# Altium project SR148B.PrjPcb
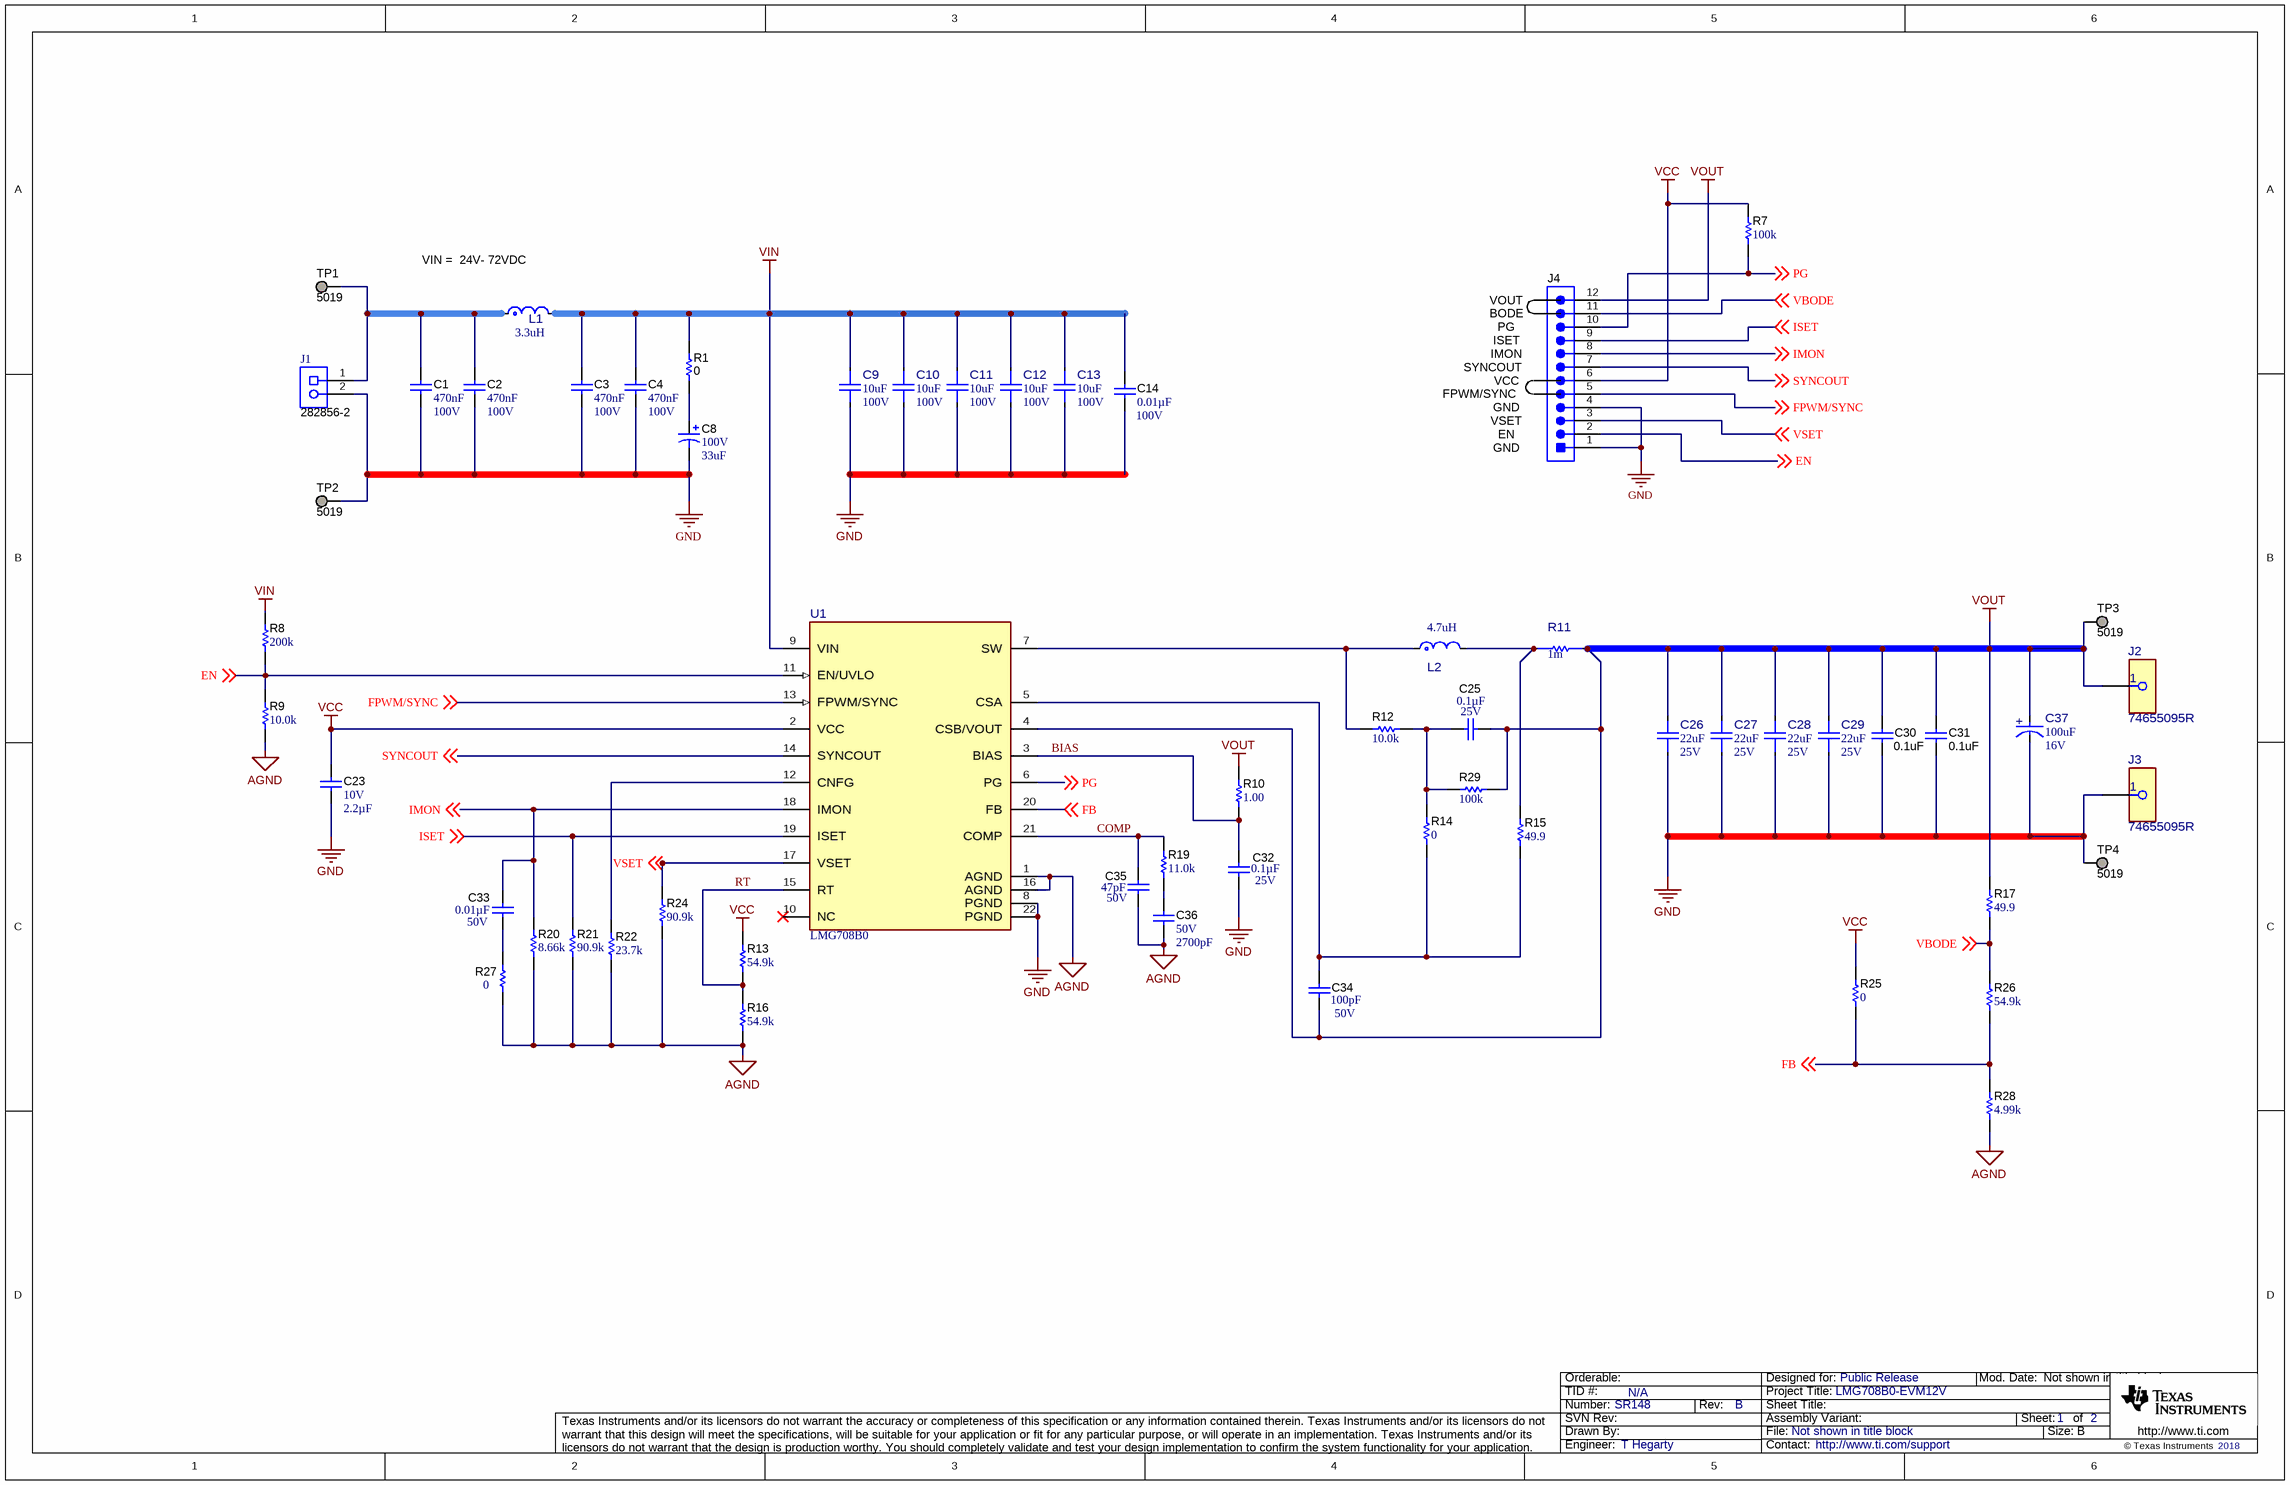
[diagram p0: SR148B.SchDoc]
TID: N/A; TechSupport: http://www.ti.com/support; Sheet Title: =title: LMG; SCH_Rev: B; PRJ_Title: LMG708B0-EVM12V; PRJ_Number: SR148; PRJ_Engineer: T Hegarty; PRJ_Customer: Public Release; PCB_Rev: B; PCB_Layout: M.Figueroa; CopyrightYear: 2018
2 sheets, 90 parts. Net scope: global (net labels, ports and power ports of the same name join across sheets).
Board file: SR148B.PcbDoc
Sheets:
  SR148B.SchDoc
  SR148B_Hardware.SchDoc

## Sheet SR148B.SchDoc
size 431 x 279 mm; Date: Not shown in title block; ApprovedBy: Not shown in title block; CheckedBy: Not shown in title block; Author: Not shown in title block; CompanyName: Not shown in title block; Engineer: Not shown in title block; Organization: Not shown in title block; Address1: Not shown in title block; Address2: Not shown in title block; Address3: Not shown in title block; Address4: Not shown in title block; DocumentNumber: 3; Revision: Use project parameter SCH_Rev; SheetNumber: 1; SheetTotal: 2; PageSetup: Record=PageOptions¦CenterHorizontal=True¦CenterVertical=True¦PrintScale=1.00¦XCorrection=1.00¦YCorrection=1.00¦PrintKind=0¦BorderSize=5000000¦LeftOffset=0¦BottomOffset=0¦Orientation=2¦PaperLength=1000¦PaperWidth=1000¦Scale=100¦PaperSource=15¦PrintQuality=600¦MediaType=1¦DitherType=10¦PaperKind=Letter¦PrintScaleMode=1

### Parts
C1  Cap_F: 470nF  VDC_V: 100V  [0805_HV]  (hidden comment: GRM21BR72A474KA73L)
C2  Cap_F: 470nF  VDC_V: 100V  [0805_HV]  (hidden comment: GRM21BR72A474KA73L)
C3  Cap_F: 470nF  VDC_V: 100V  [0805_HV]  (hidden comment: GRM21BR72A474KA73L)
C4  Cap_F: 470nF  VDC_V: 100V  [0805_HV]  (hidden comment: GRM21BR72A474KA73L)
C8  VDC_V: 100V  ValueDisplayed: 33uF  [SM_RADIAL_G]  (hidden comment: EEE-FK2A330P)
C9  ValueDisplayed: 10uF  VDC_V: 100V  [FP-GRM32EC72A106KE05L_1210-MFG]  (hidden comment: GRM32EC72A106KE05L)
C10  ValueDisplayed: 10uF  VDC_V: 100V  [FP-GRM32EC72A106KE05L_1210-MFG]  (hidden comment: GRM32EC72A106KE05L)
C11  ValueDisplayed: 10uF  VDC_V: 100V  [FP-GRM32EC72A106KE05L_1210-MFG]  (hidden comment: GRM32EC72A106KE05L)
C12  ValueDisplayed: 10uF  VDC_V: 100V  [FP-GRM32EC72A106KE05L_1210-MFG]  (hidden comment: GRM32EC72A106KE05L)
C13  ValueDisplayed: 10uF  VDC_V: 100V  [FP-GRM32EC72A106KE05L_1210-MFG]  (hidden comment: GRM32EC72A106KE05L)
C14  Value2: 100V  ValueDisplayed: 0.01µF  [0603L]  (hidden comment: CGA3E2X8R2A103K080AD)
C23  VDC_V: 10V  ValueDisplayed: 2.2µF  [0402_070]  (hidden comment: GRT155C71A225KE13)
C25  VDC_V: 25V  ValueDisplayed: 0.1µF  [0402L]  (hidden comment: CGA2B3X7R1E104K050BB)
C26  ValueDisplayed: 22uF  VDC_V: 25V  [FP-CGA6P3X7R1E226M250AB_1210-MFG]  (hidden comment: CGA6P3X7R1E226M250AB)
C27  ValueDisplayed: 22uF  VDC_V: 25V  [FP-CGA6P3X7R1E226M250AB_1210-MFG]  (hidden comment: CGA6P3X7R1E226M250AB)
C28  ValueDisplayed: 22uF  VDC_V: 25V  [FP-CGA6P3X7R1E226M250AB_1210-MFG]  (hidden comment: CGA6P3X7R1E226M250AB)
C29  ValueDisplayed: 22uF  VDC_V: 25V  [FP-CGA6P3X7R1E226M250AB_1210-MFG]  (hidden comment: CGA6P3X7R1E226M250AB)
C30  ValueDisplayed: 0.1uF  [0603L]  (hidden comment: C0603C104K5RACTU)
C31  ValueDisplayed: 0.1uF  [0603L]  (hidden comment: C0603C104K5RACTU)
C32  VDC_V: 25V  ValueDisplayed: 0.1µF  [0402L]  (hidden comment: CGA2B3X7R1E104K050BB)
C33  VDC_V: 50V  ValueDisplayed: 0.01µF  [0402L]  (hidden comment: CGA2B3X8R1H103K050BB)
C34  VDC_V: 50V  ValueDisplayed: 100pF  [0402L]  (hidden comment: CGA2B2C0G1H101J050BA)
C35  ValueDisplayed: 47pF  VDC_V: 50V  [0402L]  (hidden comment: CGA2B2C0G1H470J050BA)
C36  VDC_V: 50V  ValueDisplayed: 2700pF  [0402L]  (hidden comment: GRM155R71H272KA01D)
C37  ValueDisplayed: 100uF  VDC_V: 16V  [FP-ECASD61C107M012KA0_2917-MFG]  (hidden comment: ECASD61C107M012KA0)
J1  282856-2  [TE_282856-2]
J2  74655095R  [FP-74655095R_CONN_TERM_10MM0_10MM0-MFG]
J3  74655095R  [FP-74655095R_CONN_TERM_10MM0_10MM0-MFG]
J4  TSW-112-07-G-S  [TSW-112-07-G-S]  (value not drawn)
L1  value 3.3uH  [FP-XGL6060-332MEC_SMT_6MM51_6MM71-MFG]  (hidden comment: XGL6060-332MEC)
L2  value 4.7uH  [FP-VCUD128T-4R7MS8_SMT_IND_13MM3_12MM8-MFG]  (hidden comment: VCUD128T-4R7MS8)
R1  ValueDisplayed: 0  [0805L]  (hidden comment: ERJ-6GEY0R00V)
R7  ValueDisplayed: 100k  [0402L]  (hidden comment: AC0402FR-07100KL)
R8  ValueDisplayed: 200k  [0603L]  (hidden comment: RC0603FR-07200KL)
R9  ValueDisplayed: 10.0k  [0402L]  (hidden comment: ERJPA2F1002X)
R10  ValueDisplayed: 1.00  [0402L]  (hidden comment: CRCW04021R00FKED)
R11  value 1m  [FP-KRL3216E-C-R001-J-T5_0612-MFG]  (hidden comment: KRL3216E-C-R001-J-T5)
R12  ValueDisplayed: 10.0k  [0402L]  (hidden comment: ERJPA2F1002X)
R13  ValueDisplayed: 54.9k  [0402L]  (hidden comment: CRCW040254K9FKED)
R14  ValueDisplayed: 0  [0402L]  (hidden comment: RK73Z1ETTP)
R15  ValueDisplayed: 49.9  [0402L]  (hidden comment: ERJ-2RKF49R9X)
R16  ValueDisplayed: 54.9k  [0402L]  (hidden comment: CRCW040254K9FKED)
R17  ValueDisplayed: 49.9  [0402L]  (hidden comment: ERJ-2RKF49R9X)
R19  ValueDisplayed: 11.0k  [0402L]  (hidden comment: CRCW040211K0FKED)
R20  ValueDisplayed: 8.66k  [0402L]  (hidden comment: CRCW04028K66FKED)
R21  ValueDisplayed: 90.9k  [0402L]  (hidden comment: CRCW040290K9FKED)
R22  ValueDisplayed: 23.7k  [0402L]  (hidden comment: CRCW040223K7FKED)
R24  ValueDisplayed: 90.9k  [0402L]  (hidden comment: CRCW040290K9FKED)
R25  ValueDisplayed: 0  [0402L]  (hidden comment: RK73Z1ETTP)
R26  ValueDisplayed: 54.9k  [0402L]  (hidden comment: CRCW040254K9FKED)
R27  ValueDisplayed: 0  [0402L]  (hidden comment: RK73Z1ETTP)
R28  ValueDisplayed: 4.99k  [0402L]  (hidden comment: ERA-2AEB4991X)
R29  ValueDisplayed: 100k  [0402L]  (hidden comment: AC0402FR-07100KL)
TP1  5019  [Keystone_5019]
TP2  5019  [Keystone_5019]
TP3  5019  [Keystone_5019]
TP4  5019  [Keystone_5019]
U1  LMG708B0VBTR  [VBT0022B-MFG]  (value not drawn)

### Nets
AGND: C35.2 C36.2 R9.1 R16.1 R20.1 R21.1 R22.1 R24.1 R27.1 R28.1 U1.1(AGND) U1.16(AGND)
GND: C1.2 C2.2 C3.2 C4.2 C8.2(-) C9.2 C10.2 C11.2 C12.2 C13.2 C14.2 C23.2 C26.1 C27.1 C28.1 C29.1 C30.2 C31.2 C32.2 C37.1(CATHODE) J1.2 J3.1 J4.1 J4.4 TP2.1 TP4.1 U1.8(PGND) U1.22(PGND)
VCC: C23.1 J4.6 R7.2 R13.2 R25.2 U1.2(VCC)
VIN: C3.1 C4.1 C9.1 C10.1 C11.1 C12.1 C13.1 C14.1 L1.2 R1.2 R8.2 U1.9(VIN)
VOUT: C25.2 C26.2 C27.2 C28.2 C29.2 C30.1 C31.1 C34.2 C37.2(ANODE) J2.1 J4.12 R10.2 R11.2 R17.2 R29.1 TP3.1 U1.4(CSB/VOUT)
BIAS: C32.1 R10.1 U1.3(BIAS)
COMP: C35.1 R19.2 U1.21(COMP)
EN: J4.2 R8.1 R9.2 U1.11(EN/UVLO) ; off-sheet EN
FB: R25.1 R26.1 R28.2 U1.20(FB) ; off-sheet FB
FPWM/SYNC: J4.5 U1.13(FPWM/SYNC) ; off-sheet FPWM/SYNC
IMON: C33.2 J4.8 R20.2 U1.18(IMON) ; off-sheet IMON
ISET: J4.9 R21.2 U1.19(ISET) ; off-sheet ISET
PG: J4.10 R7.1 U1.6(PG) ; off-sheet PG
RT: R13.1 R16.2 U1.15(RT)
SYNCOUT: J4.7 U1.14(SYNCOUT) ; off-sheet SYNCOUT
VBODE: J4.11 R17.1 R26.2 ; off-sheet VBODE
VSET: J4.3 R24.2 U1.17(VSET) ; off-sheet VSET
NetC1_1: C1.1 C2.1 J1.1 L1.1 TP1.1
NetC8_1: C8.1(+) R1.1
NetC25_1: C25.1 R12.2 R14.2 R29.2
NetC33_1: C33.1 R27.2
NetC34_1: C34.1 R14.1 R15.1 U1.5(CSA)
NetC36_1: C36.1 R19.1
NetL2_1: L2.1 R12.1 U1.7(SW)
NetL2_2: L2.2 R11.1 R15.2
NetR22_2: R22.2 U1.12(CNFG)

Not connected (* = marked no-connect by the designer): U1 10(NC)*

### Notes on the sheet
- (near L1) VIN =  24V- 72VDC
- VOUT
- SYNCOUT
- BODE
- PG
- IMON
- ISET
- FPWM/SYNC
- VCC
- EN
- GND
- VSET

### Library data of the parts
C1-C4 = CMP-0008374-2: CAP, CERM, 0.47 uF, 100 V, +/- 10%, X7R, 0805; Manufacturer: MuRata; TaMin_C: -55°C; Polarized: N; SizeAreaWB_mm2: 6.75; Value1: Unknown; U/M: EA; Value: 0.47uF; TaMax_C: 125°C; SizeZ_mm: 1.45; SizeX_mm: 2; SizeY_mm: 1.25; Cap_Case: 0805; SizeArea_mm2: 2.5; AEC Category: Q200
C8 = CMP-0011203-2: CAP, AL, 33 uF, 100 V, +/- 20%, 0.7 ohm, AEC-Q200 Grade 2, SMD; Manufacturer: Panasonic; TaMin_C: -55°C; ESR_ohm: 0.7; Polarized: Y; SizeAreaWB_mm2: 172.2; Value1: 0.7 ohm; U/M: EA; Value: 33uF; TaMax_C: 105°C; SizeZ_mm: 10.2; SizeX_mm: 12; SizeY_mm: 10.3; Cap_Case: G; SizeArea_mm2: 123.6; CompType: Capacitor; Cap_F: 33µF; IRMS_A: 200mA; AEC Grade: 2; AEC Category: Q200
C9-C13 = CMP-0087970-1: 10µF ±10% 100V Ceramic Capacitor X7S 1210 (3225 Metric); Manufacturer: Murata; Symbol Name: SYM-GRM32EC72A106KE05L; AEC Qualified: No; TempCo: 22%; SizeZ_mm: 2.7mm
C14 = CMP-0080063-1: CAP, CERM, 0.01 µF, 100 V,+/- 10%, X8R, AEC-Q200 Grade 0, 0603; Manufacturer: TDK; TaMin_C: -55°C; Polarized: N; SizeAreaWB_mm2: 4.68; U/M: EA; Value: 0.01uF; TaMax_C: 150°C; SizeZ_mm: 1; SizeX_mm: 1.6; SizeY_mm: 0.8; Cap_Case: 0603; SizeArea_mm2: 1.28; AEC Qualified: Y; Cap_F: 10nF; AEC Grade: 0; AEC Category: Q200
C23 = CMP-0086250-1: CAP, CERM, 2.2 µF, 10 V,+/- 10%, X7S, AEC-Q200 Grade 1, 0402; Manufacturer: MuRata; Polarized: N; TaMin_C: -55°C; SizeY_mm: 0.5; SizeX_mm: 1; TaMax_C: 125°C; AEC Qualified: Y; Cap_Case: 0402; Value: 2.2uF; SizeAreaWB_mm2: 3; SizeZ_mm: 0.7; U/M: EA; AEC Category: Q200
C25 C32 = CMP-0080610-1: CAP, CERM, 0.1 µF, 25 V,+/- 10%, X7R, AEC-Q200 Grade 1, 0402; Manufacturer: TDK; TaMin_C: -55°C; Polarized: N; SizeAreaWB_mm2: 3; U/M: EA; Value: 0.1uF; TaMax_C: 125°C; SizeZ_mm: 0.6; SizeX_mm: 1; SizeY_mm: 0.5; Cap_Case: 0402; AEC Qualified: Y; Cap_F: 100nF; AEC Category: Q200
C26-C29 = CMP-0036912-1: Cap Ceramic 22uF 25V X7R 20% Pad SMD 1210 +125°C Automotive T/R; Manufacturer: TDK; AEC Grade: Grade 1; AEC Qualified: Yes; Cap_F: 22µF; SizeZ_mm: 2.8mm; TempCo: 15%; Tolerance_%: 0.2%; Value: 22µF
C30 = CMP-0006861-4: CAP, CERM, 0.1 uF, 50 V, +/- 10%, X7R, 0603; Manufacturer: Kemet; TaMin_C: -55°C; Polarized: N; SizeAreaWB_mm2: 4.68; Value1: Unknown; U/M: EA; Value: 0.1uF; TaMax_C: 125°C; SizeZ_mm: 1; SizeX_mm: 1.6; SizeY_mm: 0.8; Cap_Case: 0603; Value2: 50V; SizeArea_mm2: 1.28; Cap_F: 100nF; AEC Category: Q200
C31 = CMP-0006861-4: CAP, CERM, 0.1 uF, 50 V, +/- 10%, X7R, 0603; Manufacturer: Kemet; Polarized: N; Value: 0.1uF; U/M: EA; Cap_F: 100nF; Value1: Unknown; VDC_V: 50V; TaMin_C: -55°C; TaMax_C: 125°C; Cap_Case: 0603; AEC Category: Q200; SizeArea_mm2: 1.28; SizeAreaWB_mm2: 4.68; SizeX_mm: 1.6; SizeY_mm: 0.8; SizeZ_mm: 1
C33 = CMP-0078224-1: CAP, CERM, 0.01 µF, 50 V,+/- 10%, X8R, AEC-Q200 Grade 0, 0402; Manufacturer: TDK; TaMin_C: -55°C; Polarized: N; SizeAreaWB_mm2: 3; U/M: EA; Value: 0.01uF; TaMax_C: 150°C; SizeZ_mm: 0.6; SizeX_mm: 1; SizeY_mm: 0.5; Cap_Case: 0402; AEC Qualified: Y; Cap_F: 10nF; AEC Grade: 0; AEC Category: Q200
C34 = CMP-0006308-2: CAP, CERM, 100 pF, 50 V, +/- 5%, C0G/NP0, AEC-Q200 Grade 1, 0402; Manufacturer: TDK; TaMin_C: -55°C; Polarized: N; SizeAreaWB_mm2: 3; Value1: Unknown; U/M: EA; Value: 100pF; TaMax_C: 125°C; SizeZ_mm: 0.6; SizeX_mm: 1; SizeY_mm: 0.5; Cap_Case: 0402; AEC Qualified: Y; AEC Category: Q200
C35 = CMP-0860832-1: CAP, CERM, 47 pF, 50 V,+/- 5%, C0G/NP0, AEC-Q200 Grade 1, 0402; Manufacturer: TDK; TaMax_C: 125°C; AEC Category: Q200; AEC Grade: 1; SizeZ_mm: 0.6; TaMin_C: -55°C; SizeArea_mm2: 0.5; Value: 47pF; AEC Qualified: Y; Polarized: N; U/M: EA; Cap_Case: 0402; SizeAreaWB_mm2: 3
C36 = CMP-0006686-2: CAP, CERM, 2700 pF, 50 V, +/- 10%, X7R, 0402; Manufacturer: MuRata; TaMin_C: -55°C; Polarized: N; SizeAreaWB_mm2: 3; Value1: Unknown; U/M: EA; Value: 2700pF; TaMax_C: 125°C; SizeZ_mm: 0.6; SizeX_mm: 1; SizeY_mm: 0.5; Cap_Case: 0402; Cap_F: 2.7nF; AEC Category: Q200
C37 = CMP-0124193-1: 100 µF 16 V Aluminum - Polymer Capacitors 2917 (7343 Metric) 12mOhm 2000 Hrs @ 105°C; Manufacturer: Murata; AEC Qualified: No; Cap_F: 100µF; IRMS_A: 4A; SizeZ_mm: 3.1mm; Tolerance_%: 20%; Dissipation Factor: 6%; Esr: 12m; Leakage Current: 480uA; Life: 2000Hours; Value: 100µF
J1 = CMP-0054978-1: Therminal Block, 5 mm, 2-pole, Tin, TH; Manufacturer: TE Connectivity; CT: TRUE; CompType: Terminal Block; CNHeader: FALSE
J2 J3 = CMP-0087729-1: WP-THRSH 8 Pin PCB Screw Terminal, 85A, Solder, M5, Vertical; Manufacturer: Wurth Electronics; ContactFinish: Tin
J4 = CMP-0075424-1: Header, 100mil, 12x1, Gold, TH; Manufacturer: Samtec; Pitch_mm: 2.54; Cert_VDE: N; Gender: Male; Cert_CSA: Y; Voltage_V: 550V; Current_A: 6.3A; Row_Count: 1; CT: False; CNHeader: True
L1 = CMP-0093175-1: Shielded Power Inductors 3.3uH 20% tol, 6.5mOhm 16.6A; Manufacturer: Coilcraft; Shrouded: true; AEC Grade: Grade 1; TaMin_C: -40°C; Ind_H: 3.3µH; Test Frequency: 1MHz; DCR_ohm: 6.5m; Isat: 6.6A; Material: Composite; Self Resonant Frequency: 24MHz; SizeZ_mm: 6.1mm; AEC Qualified: Yes; TaMax_C: +125°C
L2 = CMP-0123970-1: Power Choke Coil 4.7uH 20% 100kHz 4.7mOhm 27A AECQ200 13.3x12.8x8.0mm SMT; Manufacturer: Cyntec; AEC Grade: Grade 0; AEC Qualified: Yes; DCR_ohm: 4.7m; Ind_H: 4.7µH; Isat: 23.1A; Material: Metal Dust; SizeZ_mm: 8mm
R1 = CMP-0020616-3: RES, 0, 5%, 0.125 W, AEC-Q200 Grade 0, 0805; Manufacturer: Panasonic; Value: 0; Value_Code: 0000; Power_W: 125mW; Value2: 0.125W; VDC_V: 150V; TempCo: 600 ppm/C; EIA_Code: E24; AEC Category: Q200; AEC Qualified: Y; SizeArea_mm2: 2.5; SizeX_mm: 2; SizeY_mm: 1.25; SizeZ_mm: 1.45; SizeAreaWB_mm2: 6.75
R7 R29 = CMP-0080661-1: RES, 100 k, 1%, 0.0625 W, AEC-Q200 Grade 0, 0402; Manufacturer: Yageo America; Power_W: 62.5mW; TempCo: 100 ppm/C; SizeAreaWB_mm2: 3; Value: 100k; EIA_Code: E96; SizeX_mm: 1; SizeY_mm: 0.5; SizeZ_mm: 0.6; AEC Qualified: Y; VDC_V: 50V; AEC Grade: 0; AEC Category: Q200
R8 = CMP-0022901-4: RES, 200 k, 1%, 0.1 W, 0603; Manufacturer: Yageo; Power_W: 100mW; TempCo: 100 ppm/C; Value: 200k; EIA_Code: E96; SizeX_mm: 1.6; SizeY_mm: 0.8; SizeZ_mm: 1; Value2: 0.1W; AEC Qualified: N; VDC_V: 75V; AEC Category: Q200; SizeArea_mm2: 1.28; SizeAreaWB_mm2: 4.68
R9 R12 = CMP-0078779-1: RES, 10.0 k, 1%, 0.2 W, AEC-Q200 Grade 0, 0402; Manufacturer: Panasonic; Power_W: 200mW; TempCo: 100 ppm/C; Value_Code: 10k0; Value: 10.0k; EIA_Code: E96; Res_ohm: 10k; SizeX_mm: 1; SizeY_mm: 0.5; SizeZ_mm: 0.6; Value2: 0.2W; AEC Qualified: Y; AEC Grade: 0; AEC Category: Q200; VDC_V: 50V
R10 = CMP-0026129-2: RES, 1.00, 1%, 0.063 W, AEC-Q200 Grade 0, 0402; Manufacturer: Vishay-Dale; Power_W: 63mW; TempCo: 100 ppm/C; Value_Code: 1R00; Value: 1.00; EIA_Code: E96; Res_ohm: 1; SizeY_mm: 0.5; SizeZ_mm: 0.6; Value2: 0.063W; AEC Qualified: Y; VDC_V: 50V; AEC Category: Q200; AEC Grade: 0
R11 = CMP-0124890-1: 1 mOhms ±5% 1.5W Chip Resistor Wide 1206 (3216 Metric), 0612 Automotive AEC-Q200, Current Sense Metal Foil; Manufacturer: Susumu; AEC Grade: Grade 0; AEC Qualified: Yes; SizeZ_mm: 0.7mm; TempCo: 150ppm/°C
R13 R16 R26 = CMP-0026449-2: RES, 54.9 k, 1%, 0.063 W, AEC-Q200 Grade 0, 0402; Manufacturer: Vishay-Dale; Power_W: 63mW; TempCo: 100 ppm/C; Value_Code: 54k9; Value: 54.9k; EIA_Code: E96; SizeX_mm: 1; SizeY_mm: 0.5; SizeZ_mm: 0.6; Value2: 0.063W; AEC Qualified: Y; VDC_V: 50V; AEC Category: Q200; AEC Grade: 0
R14 R25 R27 = CMP-0027007-2: RES, 0, 5%, 0.063 W, AEC-Q200 Grade 0, 0402; Manufacturer: KOA Speer; Power_W: 63mW; TempCo: ppm/C; Value_Code: 0000; Value: 0; EIA_Code: E24; SizeX_mm: 1; SizeZ_mm: 0.6; Value2: 0.063W; SizeArea_mm2: 0.5; AEC Qualified: Y; AEC Category: Q200; U/M: EA
R15 R17 = CMP-0026703-1: RES, 49.9, 1%, 0.1 W, AEC-Q200 Grade 0, 0402; Manufacturer: Panasonic; Power_W: 100mW; TempCo: 100 ppm/C; Value_Code: 49R9; Value: 49.9; EIA_Code: E96; SizeX_mm: 1; SizeY_mm: 0.5; SizeZ_mm: 0.6; Value2: 0.1W; AEC Qualified: Y; AEC Grade: 0; AEC Category: Q200; VDC_V: 50V; U/M: EA
R19 = CMP-0025975-3: RES, 11.0 k, 1%, 0.063 W, AEC-Q200 Grade 0, 0402; Manufacturer: Vishay-Dale; Power_W: 63mW; TempCo: 100 ppm/C; Value_Code: 11k0; Value: 11.0k; EIA_Code: E96; Res_ohm: 11k; SizeX_mm: 1; SizeY_mm: 0.5; SizeZ_mm: 0.6; Value2: 0.063W; AEC Qualified: Y; VDC_V: 50V; AEC Category: Q200; AEC Grade: 0
R20 = CMP-0026591-2: RES, 8.66 k, 1%, 0.063 W, AEC-Q200 Grade 0, 0402; Manufacturer: Vishay-Dale; Power_W: 63mW; TempCo: 100 ppm/C; Value_Code: 8k66; Value: 8.66k; EIA_Code: E96; SizeX_mm: 1; SizeY_mm: 0.5; SizeZ_mm: 0.6; Value2: 0.063W; AEC Qualified: Y; VDC_V: 50V; AEC Category: Q200; AEC Grade: 0
R21 R24 = CMP-0026605-2: RES, 90.9 k, 1%, 0.063 W, AEC-Q200 Grade 0, 0402; Manufacturer: Vishay-Dale; Power_W: 63mW; TempCo: 100 ppm/C; Value_Code: 90k9; Value: 90.9k; EIA_Code: E96; SizeX_mm: 1; SizeY_mm: 0.5; SizeZ_mm: 0.6; Value2: 0.063W; AEC Qualified: Y; VDC_V: 50V; AEC Category: Q200; AEC Grade: 0
R22 = CMP-0026187-2: RES, 23.7 k, 1%, 0.063 W, AEC-Q200 Grade 0, 0402; Manufacturer: Vishay-Dale; Power_W: 63mW; TempCo: 100 ppm/C; Value_Code: 23k7; Value: 23.7k; EIA_Code: E96; SizeX_mm: 1; SizeY_mm: 0.5; SizeZ_mm: 0.6; Value2: 0.063W; AEC Qualified: Y; VDC_V: 50V; AEC Category: Q200; AEC Grade: 0
R28 = CMP-0026783-1: RES, 4.99 k, 0.1%, 0.063 W, 0402; Manufacturer: Panasonic; Power_W: 63mW; TempCo: 25 ppm/C; Value_Code: 4k99; U/M: EA; Value: 4.99k; EIA_Code: E192; SizeX_mm: 1; SizeY_mm: 0.5; SizeZ_mm: 0.6; Value2: 0.063W; AEC Qualified: N; VDC_V: 50V; AEC Category: Q200
TP1-TP4 = CMP-0055162-1: Test Point, Miniature, SMT; Manufacturer: Keystone; CNHeader: FALSE; Green_Lifecycle: Active; Green_REACh: Passed; CT: TRUE
U1 = CMP-0125338-2: LMG708B0; Manufacturer: Texas Instruments; SizeZ_mm: 0.85mm; Standoff Height: 0mm; AEC Category: Q200; CompType: IC

## Sheet SR148B_Hardware.SchDoc
size 431 x 279 mm; Date: Not shown in title block; ApprovedBy: Not shown in title block; CheckedBy: Not shown in title block; Author: Not shown in title block; CompanyName: Not shown in title block; Engineer: Not shown in title block; Organization: Not shown in title block; Address1: Not shown in title block; Address2: Not shown in title block; Address3: Not shown in title block; Address4: Not shown in title block; DocumentNumber: 4; Revision: Use project parameter SCH_Rev; SheetNumber: 2; SheetTotal: 2; PageSetup: Record=PageOptions¦CenterHorizontal=True¦CenterVertical=True¦PrintScale=1.00¦XCorrection=1.00¦YCorrection=1.00¦PrintKind=0¦BorderSize=5000000¦LeftOffset=0¦BottomOffset=0¦Orientation=2¦PaperLength=1000¦PaperWidth=1000¦Scale=100¦PaperSource=15¦PrintQuality=600¦MediaType=1¦DitherType=10¦PaperKind=Letter¦PrintScaleMode=1
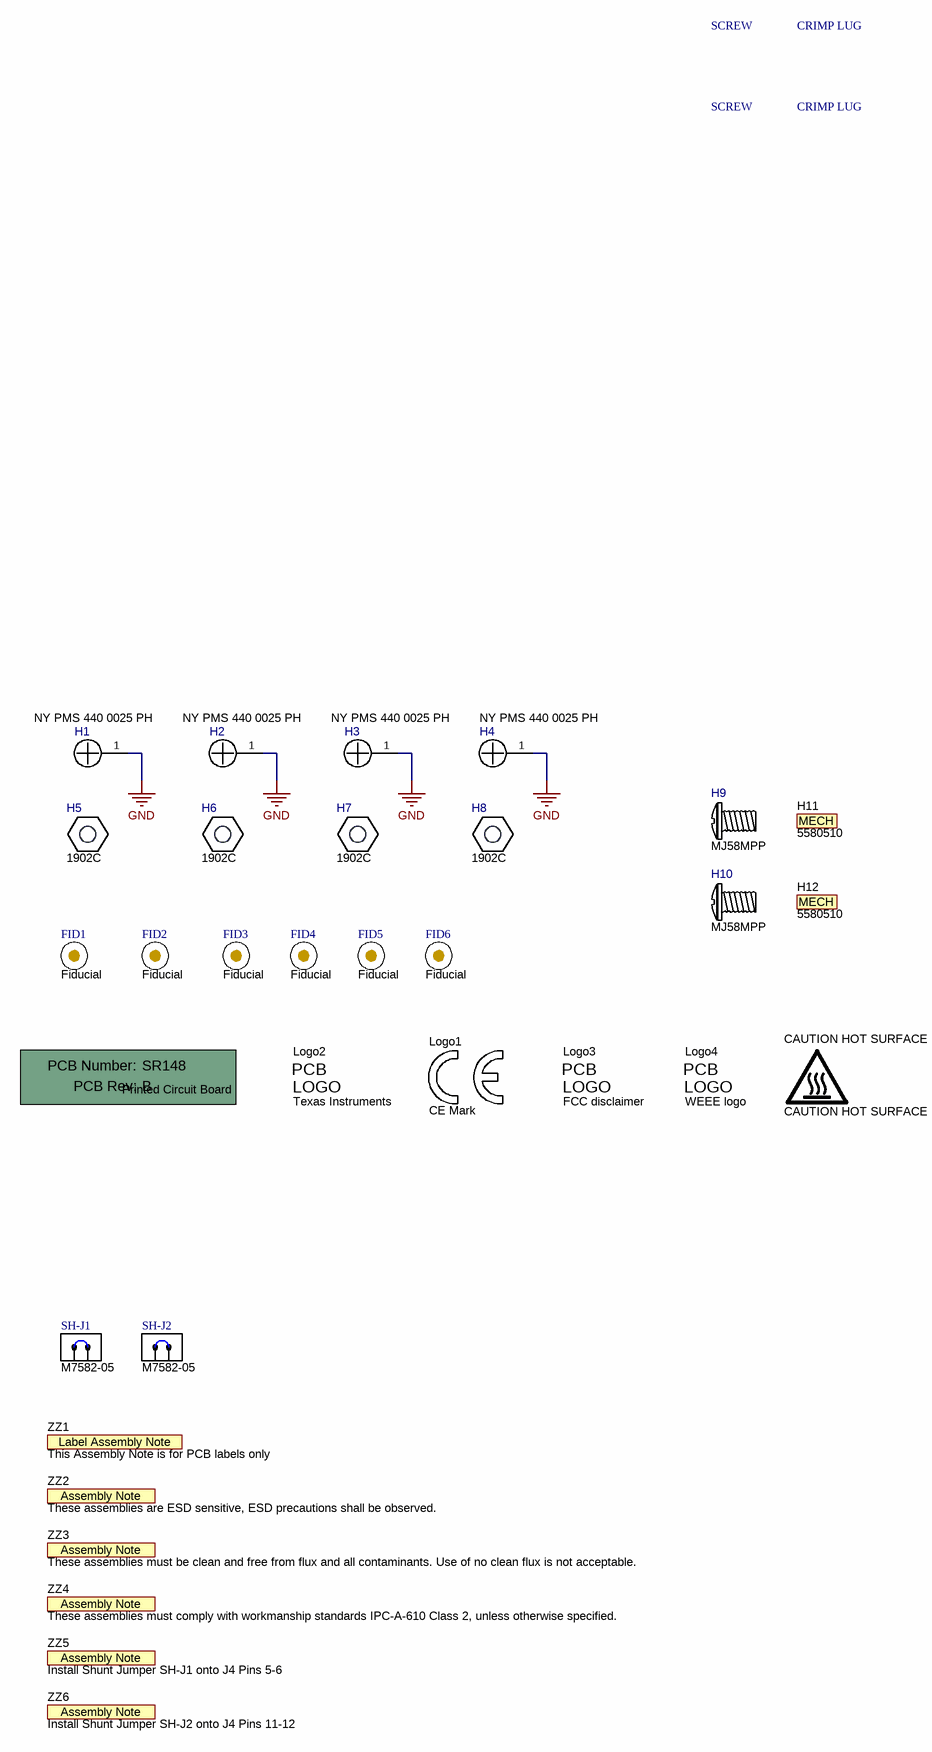
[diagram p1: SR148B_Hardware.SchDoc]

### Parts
!PCB1  Printed Circuit Board  (mechanical)
CAUTION_HOT_SURFACE  CAUTION HOT SURFACE  [IEC_HotSurface_Small]  (no BOM)
FID1  Fiducial  [Fiducial10-20]
FID2  Fiducial  [Fiducial10-20]
FID3  Fiducial  [Fiducial10-20]
FID4  Fiducial  [Fiducial10-20]
FID5  Fiducial  [Fiducial10-20]
FID6  Fiducial  [Fiducial10-20]
H1  NY PMS 440 0025 PH  [NY PMS 440 0025 PH]
H2  NY PMS 440 0025 PH  [NY PMS 440 0025 PH]
H3  NY PMS 440 0025 PH  [NY PMS 440 0025 PH]
H4  NY PMS 440 0025 PH  [NY PMS 440 0025 PH]
H5  1902C  [Keystone_1902C]
H6  1902C  [Keystone_1902C]
H7  1902C  [Keystone_1902C]
H8  1902C  [Keystone_1902C]
H9  MJ58MPP  PackageReference: SCREW  (mechanical)
H10  MJ58MPP  PackageReference: SCREW  (mechanical)
H11  5580510  PackageReference: CRIMP LUG  (mechanical)
H12  5580510  PackageReference: CRIMP LUG  (mechanical)
Logo1  CE Mark  [CE_Mark_5mm]  (no BOM)
Logo2  Texas Instruments  [TI_Stacked_Overlay_Small]  (no BOM)
Logo3  FCC disclaimer  [FCC_disclaimer]  (no BOM)
Logo4  WEEE logo  [WEEE_Minimum]  (no BOM)
SH-J1  M7582-05  [Harwin_M7582-05]
SH-J2  M7582-05  [Harwin_M7582-05]
ZZ1  This Assembly Note is for PCB labels only  [AssemblyNoteLabel]  (no BOM)
ZZ2  These assemblies are ESD sensitive, ESD precautions shall be observed.  [AssemblyNote]  (no BOM)
ZZ3  These assemblies must be clean and free from flux and all contaminants. Use of no clean flux is not acceptable.  [AssemblyNote]  (no BOM)
ZZ4  These assemblies must comply with workmanship standards IPC-A-610 Class 2, unless otherwise specified.  [AssemblyNote]  (no BOM)
ZZ5  Install Shunt Jumper SH-J1 onto J4 Pins 5-6  [AssemblyNote]  (no BOM)
ZZ6  Install Shunt Jumper SH-J2 onto J4 Pins 11-12  [AssemblyNote]  (no BOM)

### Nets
GND: H1.1 H2.1 H3.1 H4.1

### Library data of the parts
!PCB1 = CMP-0003618-2: Manufacturer: Any; PartNumber: SR148
CAUTION_HOT_SURFACE = CMP-0074837-2: IEC 61010-1 Hot Surface Warning; Manufacturer: Texas Instruments; CompType: IC; AEC Category: Q200; SymbolCreator: a0412235
FID1-FID6 = CMP-0077181-1: Fiducial mark.  There is nothing to buy or mount.
H1-H4 = CMP-0003617-1: Machine Screw, Round, #4-40 x 1/4, Nylon, Philips panhead; Manufacturer: B&F Fastener Supply; CompType: Hardware
H5-H8 = CMP-0003610-1: Standoff, Hex, 0.5"L #4-40 Nylon; Manufacturer: Keystone; CompType: Hardware
H9 H10 = CMP-0003867-1: MACHINE SCREW PAN PHILLIPS M5, 8mm long; Manufacturer: Kanebridge; CompType: Hardware
H11 H12 = CMP-0003977-1: CONN RING CIRC 7AWG M5 CRIMP; Manufacturer: Wurth Elektronik; Key: 0503518000; CompType: Receptacle
Logo1 = CMP-0074844-1: Manufacturer: Texas Instruments; SymbolCreator: a0412235; AEC Category: Q200; CompType: IC
Logo2 = CMP-0074838-1: Texas Instrument Corporate Signature; SymbolCreator: a0412235; Lib Reference: TI_Logo
Logo3 = CMP-0074847-1: FCC_disclaimer
Logo4 = CMP-0074769-1: Manufacturer: Texas Instruments; AEC Category: Q200; CompType: IC
SH-J1 SH-J2 = CMP-0078738-1: Single Operation 2.54mm Pitch Open Top Jumper Socket; Manufacturer: Harwin
ZZ1 = CMP-0003616-3
ZZ2 = CMP-0077236-1
ZZ3 = CMP-0077237-1
ZZ4 = CMP-0077238-1
ZZ5 ZZ6 = CMP-0077238-1: These assemblies must comply with workmanship standards IPC-A-610 Class 2, unless otherwise specified.

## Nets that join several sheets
GND: SR148B (28 pins), SR148B_Hardware (H1.1 H2.1 H3.1 H4.1)

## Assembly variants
001: not fitted C25 R12 R13 R14 R21 R24 R25 R29; alternate parts C8 -> CMP-0011203-2, R20 -> CMP-0026591-2, C33 -> CMP-0006324-2, R16 -> CMP-0026449-2, R22 -> CMP-0026683-1, R19 -> CMP-0025978-3, C36 -> CMP-0006683-2
002: not fitted C25 R9 R12 R14 R21 R25 R29; alternate parts R19 -> CMP-0026284-2, C36 -> CMP-0006412-2
003: not fitted C25 R9 R12 R14 R25 R29; alternate parts R19 -> CMP-0025993-3, C36 -> CMP-0006676-2, R11 -> CMP-0124890-1, C26 -> CMP-0096011-1, C27 -> CMP-0096011-1, C28 -> CMP-0096011-1, C29 -> CMP-0096011-1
